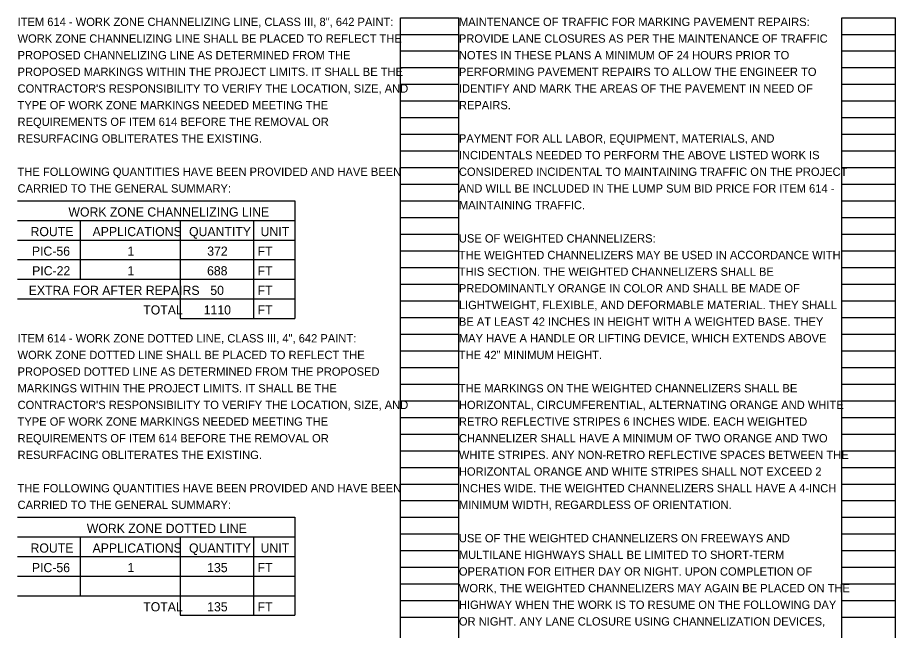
# Model space of a CAD drawing. Extents: x 24172 to 24226.9, y 11011.9 to 11091.2.
# Drawn here: x 24212.19 to 24226.95, y 11022.73 to 11033.04 of the extents above; entities that cross this region are included whole.
import ezdxf

# ---------------------------------------------------------------- set-up
doc = ezdxf.new("R2010")
doc.units = 0
doc.layers.add('SC_Scratch1', color=7, linetype='Continuous')
doc.layers.add('SH_Data', color=7, linetype='Continuous')

msp = doc.modelspace()

# ---------------------------------------------------------------- linework, layer by layer
at = {"layer": 'SH_Data'}
for p, q in [((24218.63, 11012.874), (24218.63, 11033.034)), ((24218.63, 11033.034), (24219.61, 11033.034)), ((24219.61, 11012.874), (24219.61, 11033.034)), ((24226.05, 11012.874), (24226.05, 11033.034)), ((24226.05, 11033.034), (24226.95, 11033.034)), ((24226.95, 11012.874), (24226.95, 11033.034)), ((24218.63, 11032.754), (24219.61, 11032.754)), ((24226.05, 11032.754), (24226.95, 11032.754)), ((24218.63, 11032.474), (24219.61, 11032.474)), ((24226.05, 11032.474), (24226.95, 11032.474)), ((24218.63, 11032.194), (24219.61, 11032.194)), ((24226.05, 11032.194), (24226.95, 11032.194)), ((24218.63, 11031.914), (24219.61, 11031.914)), ((24226.05, 11031.914), (24226.95, 11031.914)), ((24218.63, 11031.634), (24219.61, 11031.634)), ((24226.05, 11031.634), (24226.95, 11031.634)), ((24218.63, 11031.354), (24219.61, 11031.354)), ((24226.05, 11031.354), (24226.95, 11031.354)), ((24218.63, 11031.074), (24219.61, 11031.074)), ((24226.05, 11031.074), (24226.95, 11031.074)), ((24218.63, 11030.794), (24219.61, 11030.794)), ((24226.05, 11030.794), (24226.95, 11030.794)), ((24218.63, 11030.514), (24219.61, 11030.514)), ((24226.05, 11030.514), (24226.95, 11030.514)), ((24218.63, 11030.234), (24219.61, 11030.234)), ((24226.05, 11030.234), (24226.95, 11030.234)), ((24212.19, 11029.954), (24216.851, 11029.954)), ((24216.851, 11029.954), (24216.851, 11027.978)), ((24218.63, 11029.954), (24219.61, 11029.954)), ((24226.05, 11029.954), (24226.95, 11029.954)), ((24212.19, 11029.625), (24216.851, 11029.625)), ((24213.244, 11029.625), (24213.244, 11028.636)), ((24214.924, 11029.625), (24214.924, 11027.978)), ((24216.159, 11029.625), (24216.159, 11027.978)), ((24218.63, 11029.674), (24219.61, 11029.674)), ((24226.05, 11029.674), (24226.95, 11029.674)), ((24212.19, 11029.295), (24216.851, 11029.295)), ((24218.63, 11029.394), (24219.61, 11029.394)), ((24226.05, 11029.394), (24226.95, 11029.394)), ((24218.63, 11029.114), (24219.61, 11029.114)), ((24226.05, 11029.114), (24226.95, 11029.114)), ((24212.19, 11028.966), (24216.851, 11028.966)), ((24218.63, 11028.834), (24219.61, 11028.834)), ((24226.05, 11028.834), (24226.95, 11028.834)), ((24212.19, 11028.636), (24216.851, 11028.636)), ((24218.63, 11028.554), (24219.61, 11028.554)), ((24226.05, 11028.554), (24226.95, 11028.554)), ((24212.19, 11028.307), (24216.851, 11028.307)), ((24218.63, 11028.274), (24219.61, 11028.274)), ((24226.05, 11028.274), (24226.95, 11028.274)), ((24214.924, 11027.978), (24216.851, 11027.978)), ((24218.63, 11027.994), (24219.61, 11027.994)), ((24226.05, 11027.994), (24226.95, 11027.994)), ((24218.63, 11027.714), (24219.61, 11027.714)), ((24226.05, 11027.714), (24226.95, 11027.714)), ((24218.63, 11027.434), (24219.61, 11027.434)), ((24226.05, 11027.434), (24226.95, 11027.434)), ((24218.63, 11027.154), (24219.61, 11027.154)), ((24226.05, 11027.154), (24226.95, 11027.154)), ((24218.63, 11026.874), (24219.61, 11026.874)), ((24226.05, 11026.874), (24226.95, 11026.874)), ((24218.63, 11026.594), (24219.61, 11026.594)), ((24226.05, 11026.594), (24226.95, 11026.594)), ((24218.63, 11026.314), (24219.61, 11026.314)), ((24226.05, 11026.314), (24226.95, 11026.314)), ((24218.63, 11026.034), (24219.61, 11026.034)), ((24226.05, 11026.034), (24226.95, 11026.034)), ((24218.63, 11025.754), (24219.61, 11025.754)), ((24226.05, 11025.754), (24226.95, 11025.754)), ((24218.63, 11025.474), (24219.61, 11025.474)), ((24226.05, 11025.474), (24226.95, 11025.474)), ((24218.63, 11025.194), (24219.61, 11025.194)), ((24226.05, 11025.194), (24226.95, 11025.194)), ((24218.63, 11024.914), (24219.61, 11024.914)), ((24226.05, 11024.914), (24226.95, 11024.914)), ((24212.19, 11024.634), (24216.851, 11024.634)), ((24216.851, 11024.634), (24216.851, 11022.987)), ((24218.63, 11024.634), (24219.61, 11024.634)), ((24226.05, 11024.634), (24226.95, 11024.634)), ((24212.19, 11024.305), (24216.851, 11024.305)), ((24213.244, 11024.305), (24213.244, 11023.316)), ((24214.924, 11024.305), (24214.924, 11022.987)), ((24216.159, 11024.305), (24216.159, 11022.987)), ((24218.63, 11024.354), (24219.61, 11024.354)), ((24226.05, 11024.354), (24226.95, 11024.354)), ((24212.19, 11023.975), (24216.851, 11023.975)), ((24218.63, 11024.074), (24219.61, 11024.074)), ((24226.05, 11024.074), (24226.95, 11024.074)), ((24218.63, 11023.794), (24219.61, 11023.794)), ((24226.05, 11023.794), (24226.95, 11023.794)), ((24212.19, 11023.646), (24216.851, 11023.646)), ((24218.63, 11023.514), (24219.61, 11023.514)), ((24226.05, 11023.514), (24226.95, 11023.514)), ((24212.19, 11023.316), (24216.851, 11023.316)), ((24218.63, 11023.234), (24219.61, 11023.234)), ((24226.05, 11023.234), (24226.95, 11023.234)), ((24214.924, 11022.987), (24216.851, 11022.987)), ((24218.63, 11022.954), (24219.61, 11022.954)), ((24226.05, 11022.954), (24226.95, 11022.954))]:
    msp.add_line(p, q, dxfattribs=at)

# ---------------------------------------------------------------- texts
at = {"layer": 'SC_Scratch1'}
for s, p in [('ITEM 614 - WORK ZONE CHANNELIZING LINE, CLASS III, 8", 642 PAINT:', (24212.19, 11032.894)), ('MAINTENANCE OF TRAFFIC FOR MARKING PAVEMENT REPAIRS:', (24219.61, 11032.894)), ('WORK ZONE CHANNELIZING LINE SHALL BE PLACED TO REFLECT THE ', (24212.19, 11032.614)), ('PROVIDE LANE CLOSURES AS PER THE MAINTENANCE OF TRAFFIC ', (24219.61, 11032.614)), ('PROPOSED CHANNELIZING LINE AS DETERMINED FROM THE ', (24212.19, 11032.334)), ('NOTES IN THESE PLANS A MINIMUM OF 24 HOURS PRIOR TO ', (24219.61, 11032.334)), ('PROPOSED MARKINGS WITHIN THE PROJECT LIMITS. IT SHALL BE THE ', (24212.19, 11032.054)), ('PERFORMING PAVEMENT REPAIRS TO ALLOW THE ENGINEER TO ', (24219.61, 11032.054)), ("CONTRACTOR'S RESPONSIBILITY TO VERIFY THE LOCATION, SIZE, AND ", (24212.19, 11031.774)), ('IDENTIFY AND MARK THE AREAS OF THE PAVEMENT IN NEED OF ', (24219.61, 11031.774)), ('TYPE OF WORK ZONE MARKINGS NEEDED MEETING THE ', (24212.19, 11031.494)), ('REPAIRS.', (24219.61, 11031.494)), ('REQUIREMENTS OF ITEM 614 BEFORE THE REMOVAL OR ', (24212.19, 11031.214)), ('RESURFACING OBLITERATES THE EXISTING.', (24212.19, 11030.934)), ('PAYMENT FOR ALL LABOR, EQUIPMENT, MATERIALS, AND ', (24219.61, 11030.934)), ('INCIDENTALS NEEDED TO PERFORM THE ABOVE LISTED WORK IS ', (24219.61, 11030.654)), ('THE FOLLOWING QUANTITIES HAVE BEEN PROVIDED AND HAVE BEEN ', (24212.19, 11030.374)), ('CONSIDERED INCIDENTAL TO MAINTAINING TRAFFIC ON THE PROJECT ', (24219.61, 11030.374)), ('CARRIED TO THE GENERAL SUMMARY:', (24212.19, 11030.094)), ('AND WILL BE INCLUDED IN THE LUMP SUM BID PRICE FOR ITEM 614 - ', (24219.61, 11030.094)), ('MAINTAINING TRAFFIC.', (24219.61, 11029.814)), ('USE OF WEIGHTED CHANNELIZERS:', (24219.61, 11029.254)), ('THE WEIGHTED CHANNELIZERS MAY BE USED IN ACCORDANCE WITH ', (24219.61, 11028.974)), ('THIS SECTION. THE WEIGHTED CHANNELIZERS SHALL BE ', (24219.61, 11028.694)), ('PREDOMINANTLY ORANGE IN COLOR AND SHALL BE MADE OF ', (24219.61, 11028.414)), ('LIGHTWEIGHT, FLEXIBLE, AND DEFORMABLE MATERIAL. THEY SHALL ', (24219.61, 11028.134)), ('BE AT LEAST 42 INCHES IN HEIGHT WITH A WEIGHTED BASE. THEY ', (24219.61, 11027.854)), ('ITEM 614 - WORK ZONE DOTTED LINE, CLASS III, 4", 642 PAINT:', (24212.19, 11027.574)), ('MAY HAVE A HANDLE OR LIFTING DEVICE, WHICH EXTENDS ABOVE ', (24219.61, 11027.574)), ('WORK ZONE DOTTED LINE SHALL BE PLACED TO REFLECT THE ', (24212.19, 11027.294)), ('THE 42" MINIMUM HEIGHT.', (24219.61, 11027.294)), ('PROPOSED DOTTED LINE AS DETERMINED FROM THE PROPOSED ', (24212.19, 11027.014)), ('MARKINGS WITHIN THE PROJECT LIMITS. IT SHALL BE THE ', (24212.19, 11026.734)), ('THE MARKINGS ON THE WEIGHTED CHANNELIZERS SHALL BE ', (24219.61, 11026.734)), ("CONTRACTOR'S RESPONSIBILITY TO VERIFY THE LOCATION, SIZE, AND ", (24212.19, 11026.454)), ('HORIZONTAL, CIRCUMFERENTIAL, ALTERNATING ORANGE AND WHITE ', (24219.61, 11026.454)), ('TYPE OF WORK ZONE MARKINGS NEEDED MEETING THE ', (24212.19, 11026.174)), ('RETRO REFLECTIVE STRIPES 6 INCHES WIDE. EACH WEIGHTED ', (24219.61, 11026.174)), ('REQUIREMENTS OF ITEM 614 BEFORE THE REMOVAL OR ', (24212.19, 11025.894)), ('CHANNELIZER SHALL HAVE A MINIMUM OF TWO ORANGE AND TWO ', (24219.61, 11025.894)), ('RESURFACING OBLITERATES THE EXISTING.', (24212.19, 11025.614)), ('WHITE STRIPES. ANY NON-RETRO REFLECTIVE SPACES BETWEEN THE ', (24219.61, 11025.614)), ('HORIZONTAL ORANGE AND WHITE STRIPES SHALL NOT EXCEED 2 ', (24219.61, 11025.334)), ('THE FOLLOWING QUANTITIES HAVE BEEN PROVIDED AND HAVE BEEN ', (24212.19, 11025.054)), ('INCHES WIDE. THE WEIGHTED CHANNELIZERS SHALL HAVE A 4-INCH ', (24219.61, 11025.054)), ('CARRIED TO THE GENERAL SUMMARY:', (24212.19, 11024.774)), ('MINIMUM WIDTH, REGARDLESS OF ORIENTATION.', (24219.61, 11024.774)), ('USE OF THE WEIGHTED CHANNELIZERS ON FREEWAYS AND ', (24219.61, 11024.214)), ('MULTILANE HIGHWAYS SHALL BE LIMITED TO SHORT-TERM ', (24219.61, 11023.934)), ('OPERATION FOR EITHER DAY OR NIGHT. UPON COMPLETION OF ', (24219.61, 11023.654)), ('WORK, THE WEIGHTED CHANNELIZERS MAY AGAIN BE PLACED ON THE ', (24219.61, 11023.374)), ('HIGHWAY WHEN THE WORK IS TO RESUME ON THE FOLLOWING DAY ', (24219.61, 11023.094)), ('OR NIGHT. ANY LANE CLOSURE USING CHANNELIZATION DEVICES, ', (24219.61, 11022.814))]:
    msp.add_text(s, height=0.14, dxfattribs=at).set_placement(p)
at = {"layer": 'SH_Data'}
for s, p in [('WORK ZONE CHANNELIZING LINE', (24213.045, 11029.691)), ('ROUTE', (24212.408, 11029.361)), ('APPLICATIONS', (24213.451, 11029.361)), ('QUANTITY', (24215.073, 11029.361)), ('UNIT', (24216.276, 11029.361)), ('PIC-56', (24212.431, 11029.032)), ('1', (24214.038, 11029.032)), ('372', (24215.379, 11029.032)), ('FT', (24216.225, 11029.032)), ('PIC-22', (24212.435, 11028.702)), ('1', (24214.038, 11028.702)), ('688', (24215.376, 11028.702)), ('FT', (24216.225, 11028.702)), ('EXTRA FOR AFTER REPAIRS', (24212.378, 11028.373)), ('50', (24215.431, 11028.373)), ('FT', (24216.225, 11028.373)), ('TOTAL', (24214.303, 11028.044)), ('1110', (24215.32, 11028.044)), ('FT', (24216.225, 11028.044)), ('WORK ZONE DOTTED LINE', (24213.354, 11024.371)), ('ROUTE', (24212.408, 11024.041)), ('APPLICATIONS', (24213.451, 11024.041)), ('QUANTITY', (24215.073, 11024.041)), ('UNIT', (24216.276, 11024.041)), ('PIC-56', (24212.431, 11023.712)), ('1', (24214.038, 11023.712)), ('135', (24215.378, 11023.712)), ('FT', (24216.225, 11023.712)), ('TOTAL', (24214.303, 11023.053)), ('135', (24215.378, 11023.053)), ('FT', (24216.225, 11023.053))]:
    msp.add_text(s, height=0.154, dxfattribs=at).set_placement(p)

doc.saveas('drawing.dxf')
